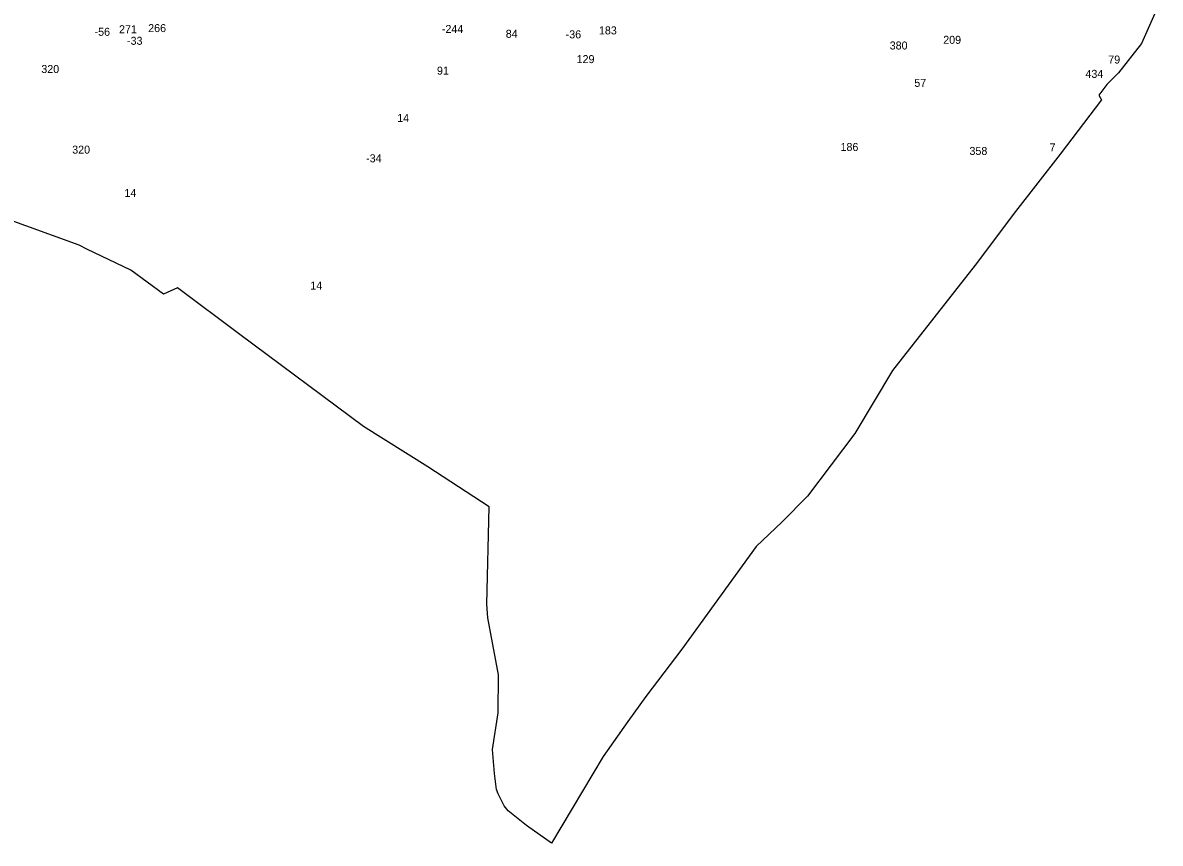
# Model space of a CAD drawing. Extents: x -784109 to -782312, y -974244 to -970866.
# Drawn here: x -783412 to -782593, y -974244 to -973653 of the extents above; entities that cross this region are included whole.
import ezdxf

# ---------------------------------------------------------------- set-up
doc = ezdxf.new("R2010")
doc.units = 0
doc.layers.add('Vrstva 13', color=7, linetype='Continuous')
doc.layers.add('Vrstva 24', color=7, linetype='Continuous')

msp = doc.modelspace()

# ---------------------------------------------------------------- linework, layer by layer
at = {"layer": 'Vrstva 13'}
for p, q in [((-782593.28, -973637.78), (-782606.89, -973667.99)), ((-782606.89, -973667.99), (-782623.35, -973689.33)), ((-782623.35, -973689.33), (-782631.78, -973697.52)), ((-782631.78, -973697.52), (-782637.42, -973705.29)), ((-782637.42, -973705.29), (-782635.55, -973708.6)), ((-782635.55, -973708.6), (-782665.27, -973747.73)), ((-782665.27, -973747.73), (-782697.47, -973789.04)), ((-782697.47, -973789.04), (-782726.55, -973827.86)), ((-783371.73, -973813.41), (-783429.39, -973792.54)), ((-783366.12, -973816.3), (-783371.73, -973813.41)), ((-783334.37, -973831.4), (-783366.12, -973816.3)), ((-782726.55, -973827.86), (-782786.08, -973903.69)), ((-783310.87, -973848.73), (-783334.37, -973831.4)), ((-783300.9, -973844.14), (-783310.87, -973848.73)), ((-783256.03, -973877.74), (-783300.9, -973844.14)), ((-783166.81, -973943.89), (-783256.03, -973877.74)), ((-782786.08, -973903.69), (-782813.2, -973949.16)), ((-783120.63, -973973.16), (-783166.81, -973943.89)), ((-782813.2, -973949.16), (-782847.27, -973994.21)), ((-783076.41, -974001.77), (-783120.63, -973973.16)), ((-783078.22, -974071.93), (-783076.41, -974001.77)), ((-782847.27, -973994.21), (-782865.49, -974012.65)), ((-782865.49, -974012.65), (-782884.12, -974030.35)), ((-782884.12, -974030.35), (-782914.45, -974072.14)), ((-783077.5, -974081.71), (-783078.22, -974071.93)), ((-782914.45, -974072.14), (-782937.75, -974104.3)), ((-783069.82, -974122.93), (-783077.5, -974081.71)), ((-782937.75, -974104.3), (-782963.73, -974138.58)), ((-783069.88, -974150.16), (-783069.82, -974122.93)), ((-782963.73, -974138.58), (-782976.57, -974156.6)), ((-783074.15, -974176.61), (-783069.88, -974150.16)), ((-782976.57, -974156.6), (-782994.48, -974181.77)), ((-783072.51, -974194.01), (-783074.15, -974176.61)), ((-782994.48, -974181.77), (-783031.56, -974244.21)), ((-783071.19, -974205.43), (-783072.51, -974194.01)), ((-783069.95, -974208.57), (-783071.19, -974205.43)), ((-783065.68, -974217.17), (-783069.95, -974208.57)), ((-783062.67, -974220.85), (-783065.68, -974217.17)), ((-783049.45, -974231.35), (-783062.67, -974220.85)), ((-783031.56, -974244.21), (-783049.45, -974231.35))]:
    msp.add_line(p, q, dxfattribs=at)

# ---------------------------------------------------------------- texts
at = {"layer": 'Vrstva 24'}
for s, p in [('-56', (-783360.556, -973662.553)), ('271', (-783342.927, -973660.722)), ('266', (-783321.949, -973659.892)), ('-244', (-783110.486, -973660.53)), ('84', (-783064.508, -973663.992)), ('183', (-782997.425, -973661.562)), ('-33', (-783337.189, -973669.028)), ('-36', (-783021.356, -973664.401)), ('209', (-782749.523, -973668.342)), ('380', (-782788.069, -973672.422)), ('129', (-783013.479, -973682.232)), ('79', (-782630.708, -973682.542)), ('320', (-783398.889, -973689.352)), ('91', (-783114.039, -973690.552)), ('434', (-782647.144, -973692.842)), ('57', (-782770.335, -973699.342)), ('14', (-783142.631, -973724.652)), ('186', (-782823.479, -973745.512)), ('7', (-782672.965, -973745.882)), ('320', (-783376.649, -973747.432)), ('-34', (-783165.072, -973753.684)), ('358', (-782730.633, -973748.372)), ('14', (-783339.021, -973778.612)), ('14', (-783205.211, -973845.342))]:
    msp.add_text(s, height=5.76, dxfattribs=at).set_placement(p)

doc.saveas('drawing.dxf')
